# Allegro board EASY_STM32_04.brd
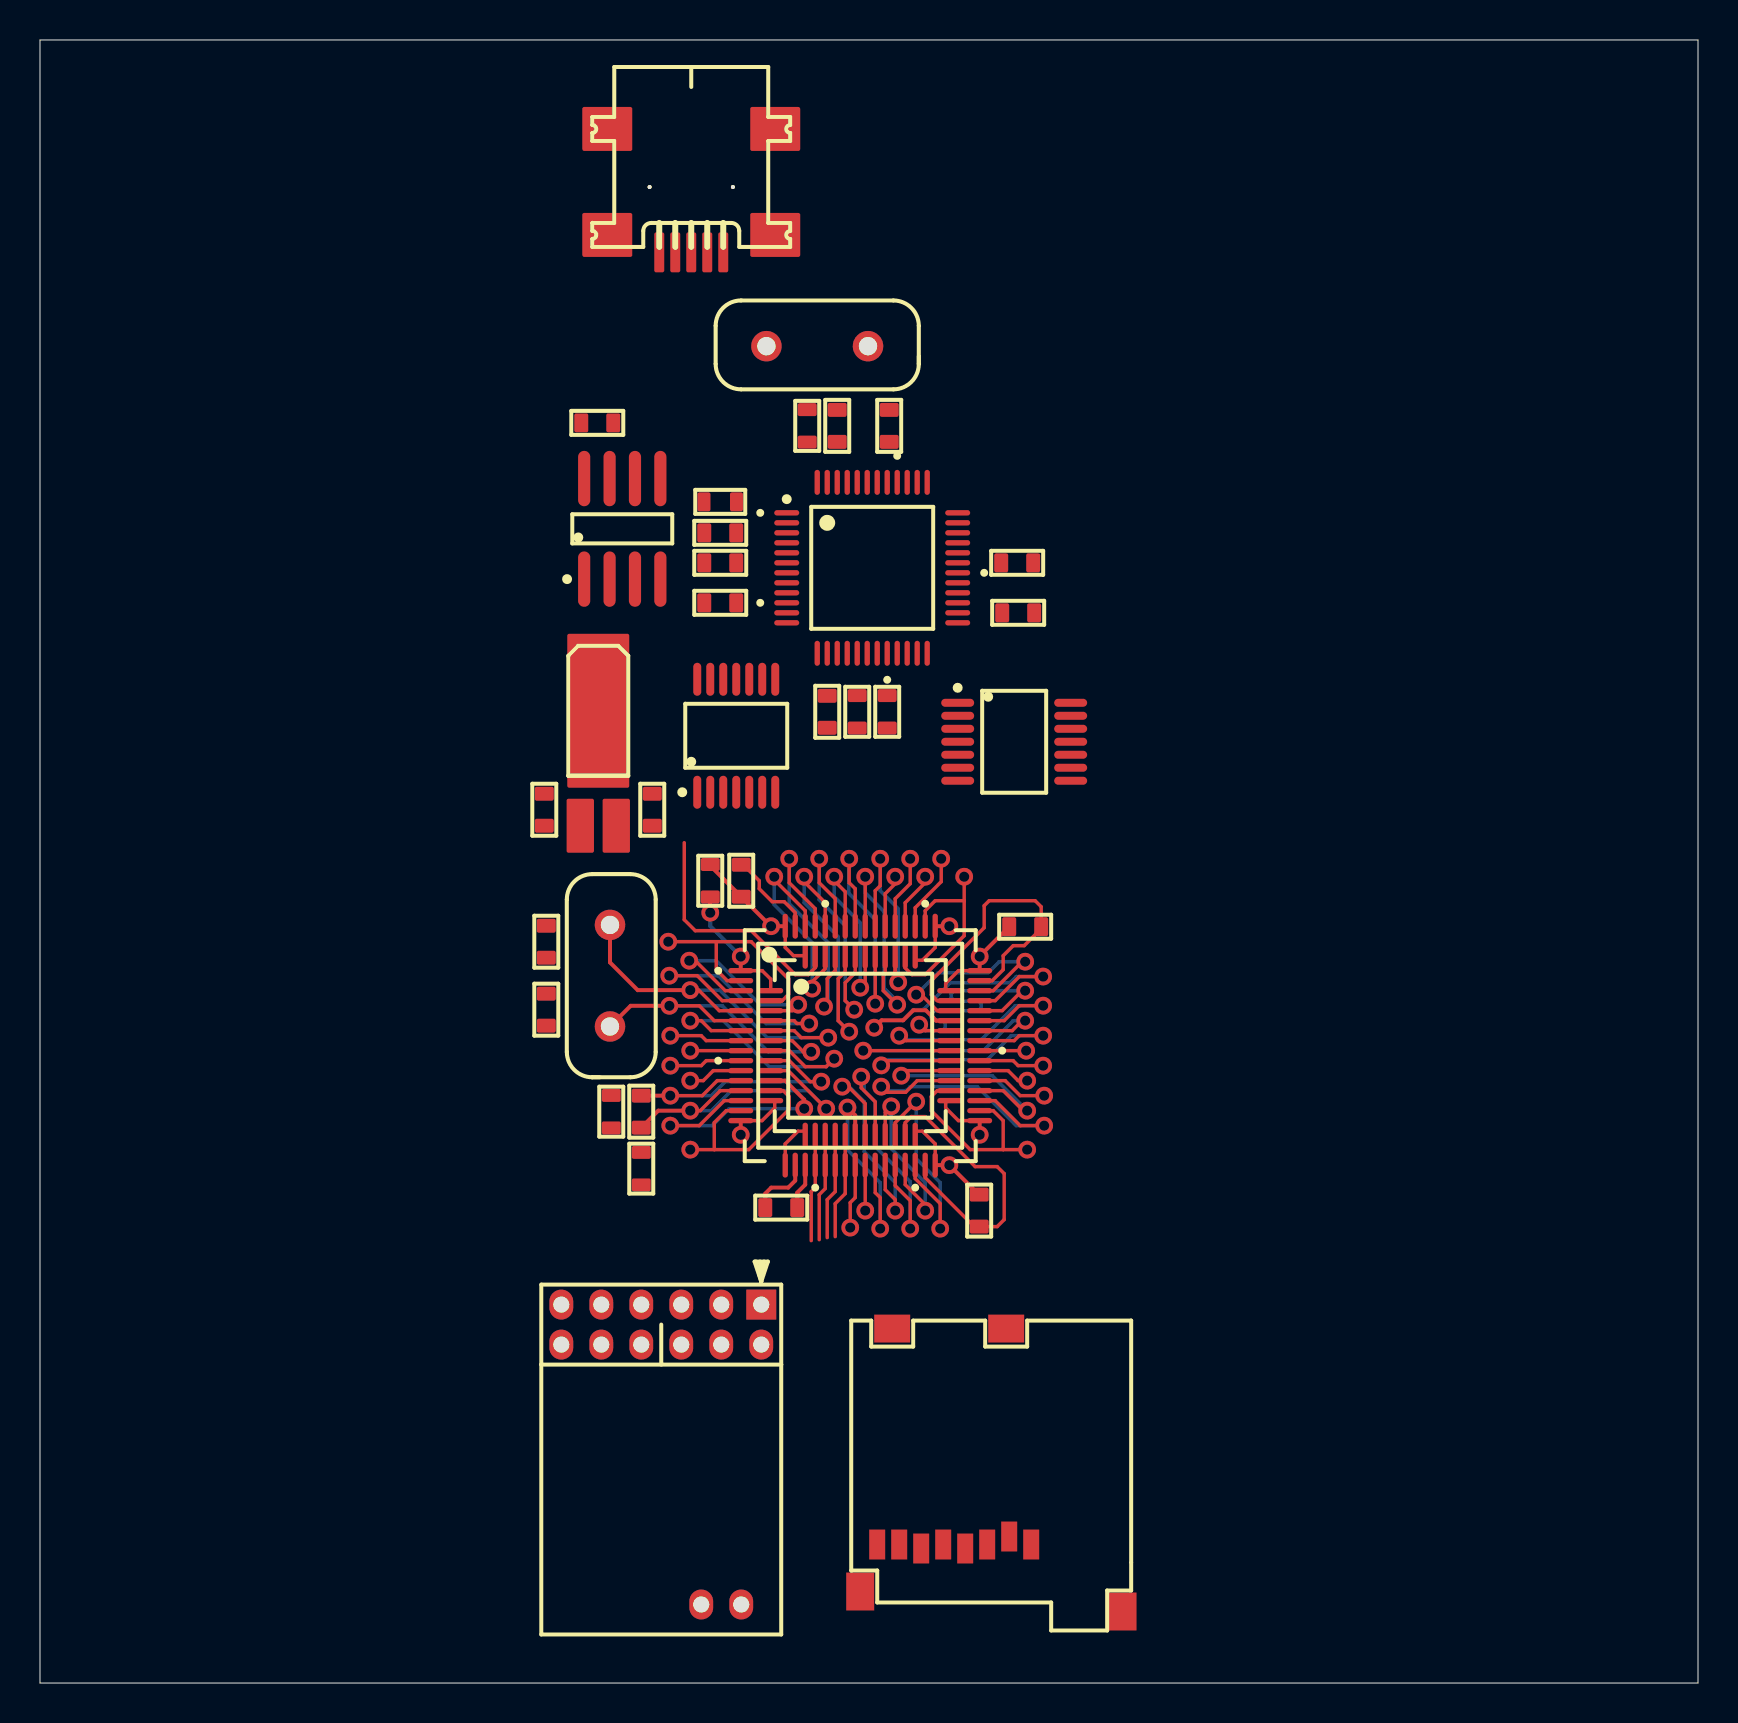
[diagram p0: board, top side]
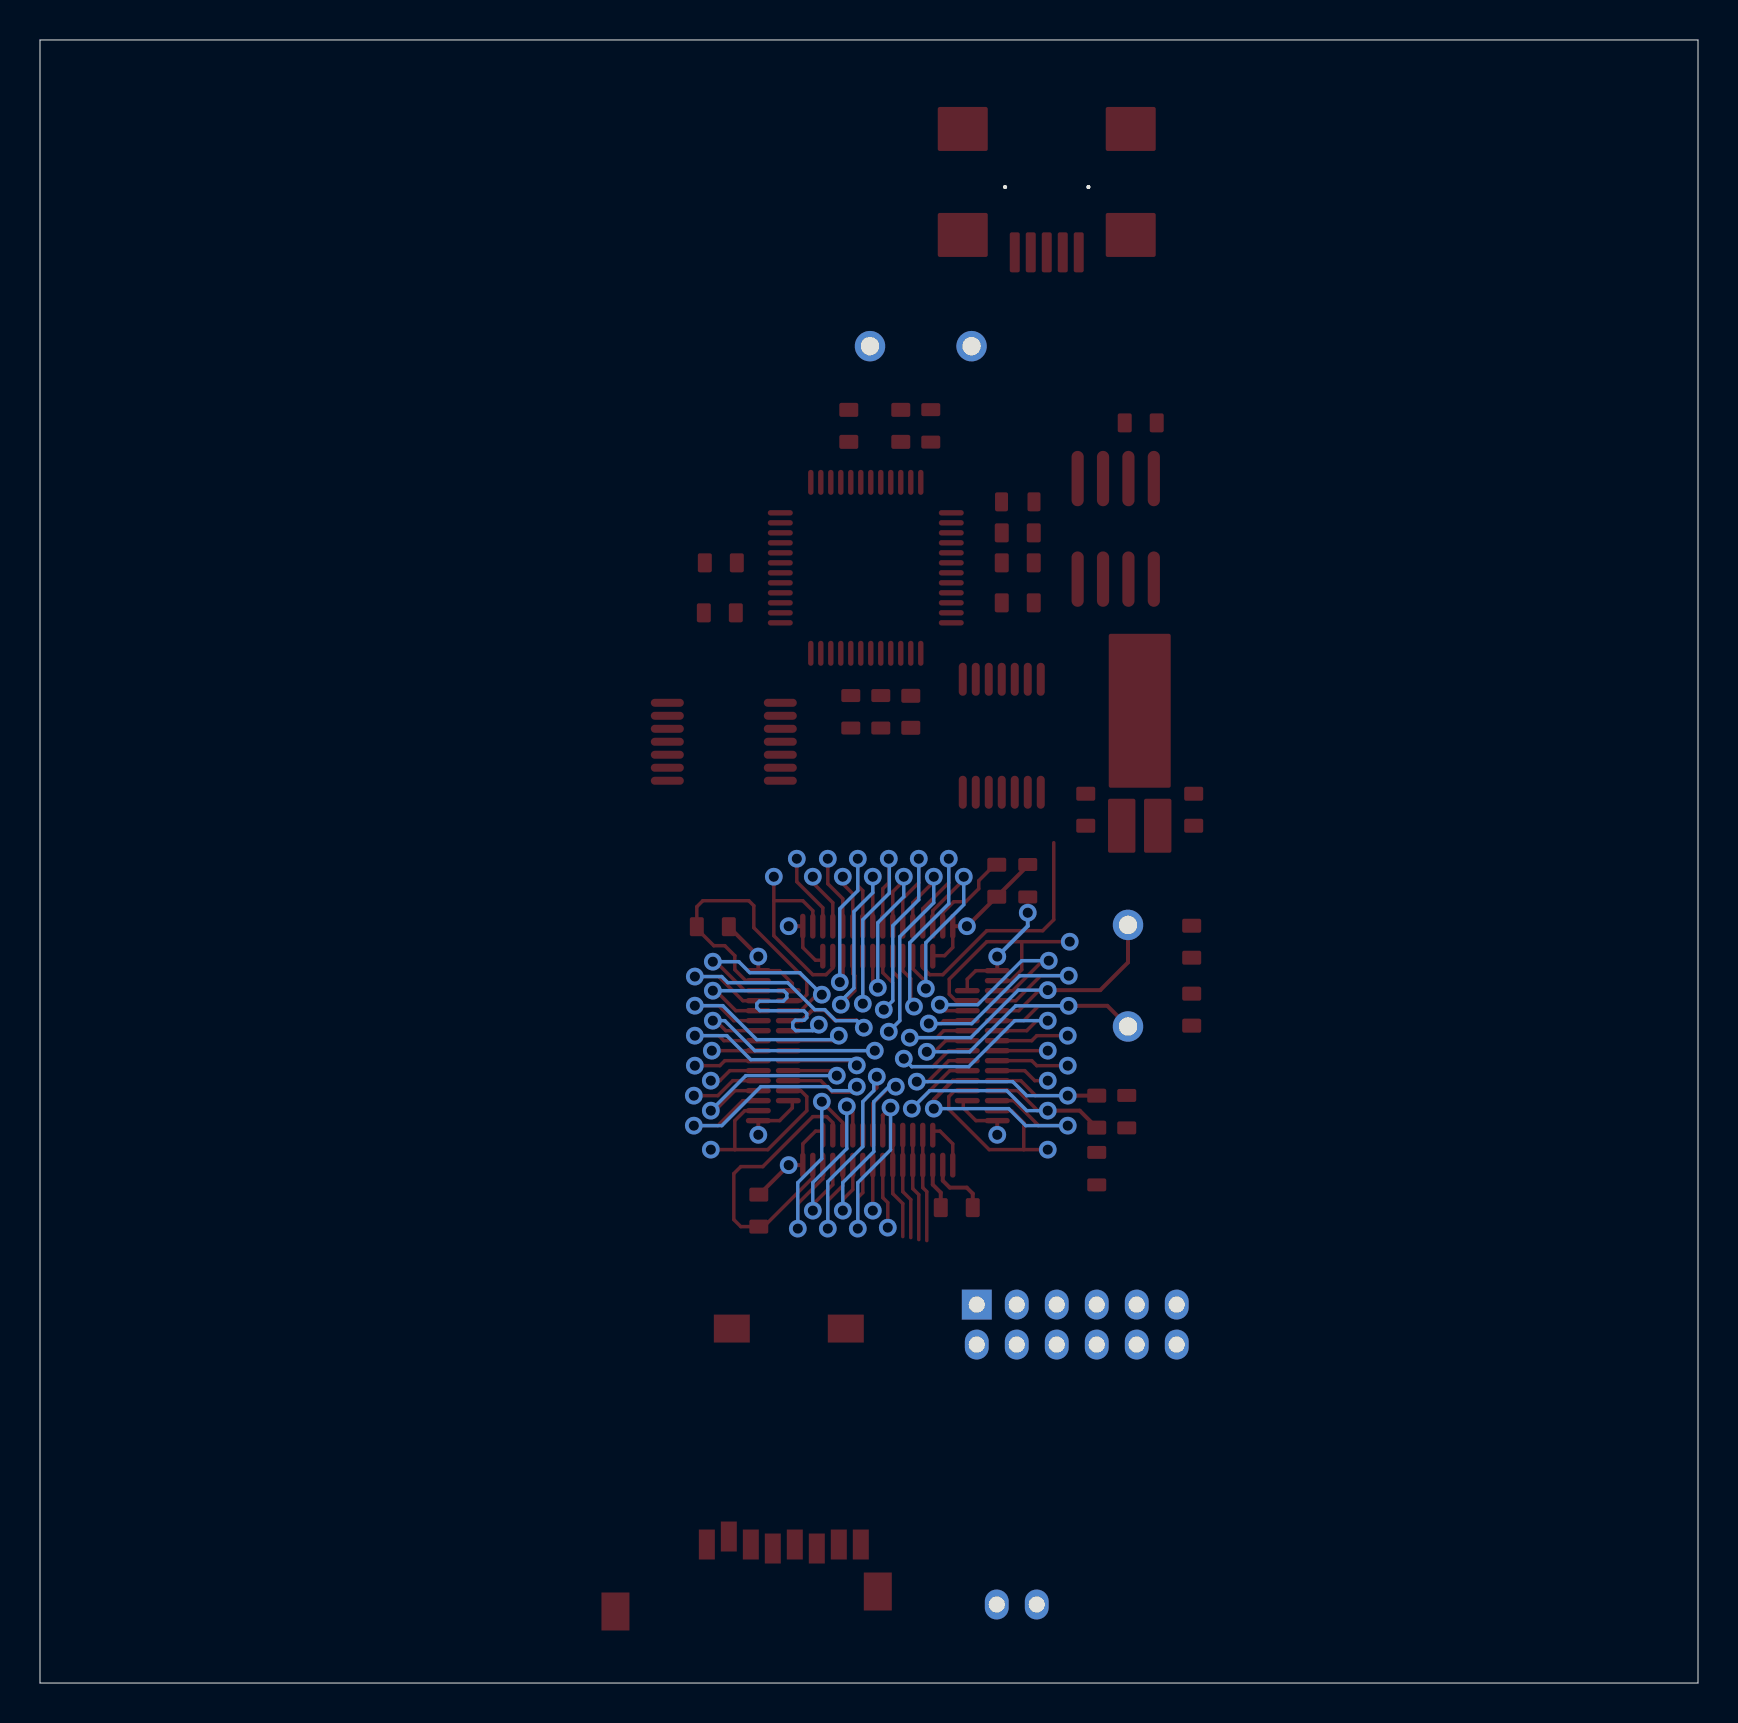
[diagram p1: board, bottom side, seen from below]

Outline 82.92 x 82.18 mm; copper layers: TOP, BOTTOM. Coordinates in mm from the lower left corner of the outline.
Outline path: 0,82.18 0,0 82.92,0 82.92,82.18 0,82.18

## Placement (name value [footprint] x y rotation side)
C1  22pF  [CAP0603_B]  25.32 37.08 270 top
C2  22p  [CAP0603_B]  25.32 33.68 90 top
C3  15p  [CAP0603_B]  25.22 43.68 90 top
C4  15p  [CAP0603_B]  30.62 43.68 90 top
C5  100n  [CAP0603_B]  30.07 28.58 90 top
C6  100n  [CAP0603_B]  46.97 23.63 270 top
C7  100n  [CAP0603_B]  49.27 37.83 0 top
C8  100n  [CAP0603_B]  35.07 40.13 90 top
C9  100n  [CAP0603_B]  37.07 23.78 180 top
C10  10u  [CAP0603_B]  27.87 63.03 0 top
C11  100n  [CAP0603_B]  34.02 57.53 180 top
C12  100n  [CAP0603_B]  42.47 62.88 90 top
C14  100n  [CAP0603_B]  34.02 54.03 180 top
C15  100n  [CAP0603_B]  39.37 48.58 270 top
C16  100n  [CAP0603_B]  48.92 53.53 0 top
C17  100n  [CAP0603_B]  48.87 56.03 0 top
C18  100n  [CAP0603_B]  39.87 62.88 90 top
C19  100n  [CAP0603_B]  34.02 56.03 180 top
J1  USB_MB  [HIROSE-US60-MB-5ST]  32.57 80.83 180 top
R1  0R  [RES0603_B]  33.52 40.13 90 top
R2  0R  [RES0603_B]  30.07 25.73 270 top
R3  0R  [RES0603_B]  28.57 28.58 270 top
R4  470R  [RES0603_B]  38.37 62.88 270 top
R7  10K  [RES0603_B]  42.37 48.58 270 top
R13  1K5  [RES0603_B]  34.02 59.08 0 top
R14  100K  [RES0603_B]  40.87 48.58 270 top
REF  val  [unnamed]  36.07 18.93 180 top
U1  STM32F103RCT6  [LQFP64_MODIFIED]  41.02 31.88 0 top
U2  STM32F100  [LQFP48L_MODIFIED]  41.02 31.88 0 top
U3  FT2232D  [LQFP48L]  41.62 55.78 0 top
U4  AT93C46-10SI-2.7  [SOIC8S1JEDECM]  29.12 57.73 0 top
U5  74LVC125A  [TSOP65P640X120-14]  48.72 47.08 270 top
U6  74LVC125A  [TSOP65P640X120-14]  34.82 47.38 0 top
U10  MICRO_SD  [MICRO_SD_PUSH]  54.57 18.13 180 top
Y1  8M  [XTAL_DIP]  28.51 32.84 90 top
Y2  32.768KHz  [RTC-CRYSTAL]  27.92 46.88 0 top
Y3  6M  [XTAL_DIP]  41.41 66.86 180 top

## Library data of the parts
C1-C9 = C1005_0: User Part Number: pn; Tolerance: RichardLC
C10-C12 C14-C19 = CAP NP_0: User Part Number: pn; Tolerance: RichardLC
J1 = CON9: User Part Number: pn; Tolerance: RichardLC
R1-R4 R7 R13 R14 = R_0: User Part Number: pn; Tolerance: RichardLC
REF = -: User Part Number: pn; Tolerance: RichardLC
U1 = STM32F103RCT6_2: User Part Number: pn; Tolerance: RichardLC
U2 = STM32F100_1: User Part Number: pn; Tolerance: RichardLC
U3 = FT2232D_0: User Part Number: pn; Tolerance: RichardLC
U4 = 93C46_2: User Part Number: pn; Tolerance: RichardLC
U5 U6 = 74HC125/LCC_0: User Part Number: pn; Tolerance: RichardLC
U10 = MOLEX_uSD_0: User Part Number: pn; Tolerance: RichardLC
Y1 Y3 = ZTB: Tolerance: ***; User Part Number: ***
Y2 = ZTA_0: User Part Number: pn; Tolerance: RichardLC

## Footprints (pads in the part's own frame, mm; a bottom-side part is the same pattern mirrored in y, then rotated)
CAP0603_B
  custom 0.175x0.175 smd: 1(-0.8,0) 2(0.8,0)
HIROSE-US60-MB-5ST
  round 0.2 hole 0.9 unplated: (-2.083,6.005) (2.083,6.005)
  custom 0.125x0.125 smd: 1(-1.6,9.271) 2(-0.8,9.271) 3(0,9.271) 4(0.8,9.271) 5(1.6,9.271)
  custom 0.55x0.55 smd: 6(-4.2,3.1) 7(4.2,3.1) 8(-4.2,8.4) 9(4.2,8.4)
LQFP48L
  oval 1.25x0.27 smd: 1(-4.275,2.75) 2(-4.275,2.25) 3(-4.275,1.75) 4(-4.275,1.25) 5(-4.275,0.75) 6(-4.275,0.25) 7(-4.275,-0.25) 8(-4.275,-0.75) 9(-4.275,-1.25) 10(-4.275,-1.75) 11(-4.275,-2.25) 12(-4.275,-2.75) 25(4.275,-2.75) 26(4.275,-2.25) 27(4.275,-1.75) 28(4.275,-1.25) 29(4.275,-0.75) 30(4.275,-0.25) 31(4.275,0.25) 32(4.275,0.75) 33(4.275,1.25) 34(4.275,1.75) 35(4.275,2.25) 36(4.275,2.75)
  oval 0.27x1.25 smd: 13(-2.75,-4.275) 14(-2.25,-4.275) 15(-1.75,-4.275) 16(-1.25,-4.275) 17(-0.75,-4.275) 18(-0.25,-4.275) 19(0.25,-4.275) 20(0.75,-4.275) 21(1.25,-4.275) 22(1.75,-4.275) 23(2.25,-4.275) 24(2.75,-4.275) 37(2.75,4.275) 38(2.25,4.275) 39(1.75,4.275) 40(1.25,4.275) 41(0.75,4.275) 42(0.25,4.275) 43(-0.25,4.275) 44(-0.75,4.275) 45(-1.25,4.275) 46(-1.75,4.275) 47(-2.25,4.275) 48(-2.75,4.275)
LQFP48L_MODIFIED
  oval 1.25x0.27 smd: 1(-4.475,2.75) 2(-4.475,2.25) 3(-4.475,1.75) 4(-4.475,1.25) 5(-4.475,0.75) 6(-4.475,0.25) 7(-4.475,-0.25) 8(-4.475,-0.75) 9(-4.475,-1.25) 10(-4.475,-1.75) 11(-4.475,-2.25) 12(-4.475,-2.75) 25(4.475,-2.75) 26(4.475,-2.25) 27(4.475,-1.75) 28(4.475,-1.25) 29(4.475,-0.75) 30(4.475,-0.25) 31(4.475,0.25) 32(4.475,0.75) 33(4.475,1.25) 34(4.475,1.75) 35(4.475,2.25) 36(4.475,2.75)
  oval 0.27x1.25 smd: 13(-2.75,-4.475) 14(-2.25,-4.475) 15(-1.75,-4.475) 16(-1.25,-4.475) 17(-0.75,-4.475) 18(-0.25,-4.475) 19(0.25,-4.475) 20(0.75,-4.475) 21(1.25,-4.475) 22(1.75,-4.475) 23(2.25,-4.475) 24(2.75,-4.475) 37(2.75,4.475) 38(2.25,4.475) 39(1.75,4.475) 40(1.25,4.475) 41(0.75,4.475) 42(0.25,4.475) 43(-0.25,4.475) 44(-0.75,4.475) 45(-1.25,4.475) 46(-1.75,4.475) 47(-2.25,4.475) 48(-2.75,4.475)
LQFP64_MODIFIED
  oval 1.25x0.27 smd: 1(-5.975,3.75) 2(-5.975,3.25) 3(-5.975,2.75) 4(-5.975,2.25) 5(-5.975,1.75) 6(-5.975,1.25) 7(-5.975,0.75) 8(-5.975,0.25) 9(-5.975,-0.25) 10(-5.975,-0.75) 11(-5.975,-1.25) 12(-5.975,-1.75) 13(-5.975,-2.25) 14(-5.975,-2.75) 15(-5.975,-3.25) 16(-5.975,-3.75) 33(5.975,-3.75) 34(5.975,-3.25) 35(5.975,-2.75) 36(5.975,-2.25) 37(5.975,-1.75) 38(5.975,-1.25) 39(5.975,-0.75) 40(5.975,-0.25) 41(5.975,0.25) 42(5.975,0.75) 43(5.975,1.25) 44(5.975,1.75) 45(5.975,2.25) 46(5.975,2.75) 47(5.975,3.25) 48(5.975,3.75)
  oval 0.27x1.25 smd: 17(-3.75,-5.975) 18(-3.25,-5.975) 19(-2.75,-5.975) 20(-2.25,-5.975) 21(-1.75,-5.975) 22(-1.25,-5.975) 23(-0.75,-5.975) 24(-0.25,-5.975) 25(0.25,-5.975) 26(0.75,-5.975) 27(1.25,-5.975) 28(1.75,-5.975) 29(2.25,-5.975) 30(2.75,-5.975) 31(3.25,-5.975) 32(3.75,-5.975) 49(3.75,5.975) 50(3.25,5.975) 51(2.75,5.975) 52(2.25,5.975) 53(1.75,5.975) 54(1.25,5.975) 55(0.75,5.975) 56(0.25,5.975) 57(-0.25,5.975) 58(-0.75,5.975) 59(-1.25,5.975) 60(-1.75,5.975) 61(-2.25,5.975) 62(-2.75,5.975) 63(-3.25,5.975) 64(-3.75,5.975)
MICRO_SD_PUSH
  rect 0.8x1.5 smd: 1(5,11.2) 2(6.1,10.8) 3(7.2,11.2) 4(8.3,11.4) 5(9.4,11.2) 6(10.5,11.4) 7(11.6,11.2) 8(12.7,11.2)
  rect 1.4x1.9 smd: G1(0.43,14.55) G2(13.55,13.55)
  rect 1.8x1.4 smd: S1(6.25,0.4) S2(11.95,0.4)
RES0603_B
  custom 0.163x0.163 smd: 1(-0.812,0) 2(0.812,0)
RTC-CRYSTAL
  custom 0.343x0.343 smd: 1(-0.9,-4) 2(0.9,-4)
  custom 0.775x0.775 smd: 3(0,1.75)
SOIC8S1JEDECM
  oval 0.61x2.77 smd: 1(-1.905,-2.515) 2(-0.635,-2.515) 3(0.635,-2.515) 4(1.905,-2.515) 5(1.905,2.515) 6(0.635,2.515) 7(-0.635,2.515) 8(-1.905,2.515)
TSOP65P640X120-14
  oval 0.4x1.65 smd: 1(-1.95,-2.825) 2(-1.3,-2.825) 3(-0.65,-2.825) 4(0,-2.825) 5(0.65,-2.825) 6(1.3,-2.825) 7(1.95,-2.825) 8(1.95,2.825) 9(1.3,2.825) 10(0.65,2.825) 11(0,2.825) 12(-0.65,2.825) 13(-1.3,2.825) 14(-1.95,2.825)
unnamed
  rect 1.5x1.5 hole 0.8: 1(0,0)
  oval 1.194x1.499 hole 0.8: 2(0,2) 3(2,0) 4(2,2) 5(4,0) 6(4,2) 7(6,0) 8(6,2) 9(8,0) 10(8,2) 11(10,0) 12(10,2) 13(1,15) 14(3,15)
XTAL_DIP
  round 1.524 hole 0.914: 1(0,0) 2(5.08,0)

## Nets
+3V3: C6.1 C7.1 C8.1 C9.1 C14.1 C15.1 C16.1 C17.1 R1.2 R2.2 R14.1 U1.19(VDD_4) U1.32(VDD_1) U1.48(VDD_2) U1.64(VDD_3) U2.24(VDD_1) U2.36(VDD_2) U2.48(VDD_3) U3.10(SI/WUA) U3.14(VCCIOA) U3.17(ADBUS6) U3.26(SI/WUB) U3.31(VCCIOB) U5.14(VCC) U10.4(VDD)
+5V: C10.1 C11.1 C12.1 R4.1 U3.3(VCC1) U3.42(VCC2) U4.8(VCC)
GND: C1.2 C2.2 C3.2 C4.2 C6.2 C7.2 C8.2 C9.2 C10.2 C11.2 C12.2 C14.2 C15.2 C16.2 C17.2 C18.2 C19.2 J1.5 J1.6 J1.7 J1.8 J1.9 R3.2 R7.2 R14.2 U1.18(VSS_4) U1.31(VSS_1) U1.47(VSS_2) U1.63(VSS_3) U2.23(VSS_1) U2.35(VSS_2) U2.47(VSS_3) U3.9(GND1) U3.18(GND2) U3.25(GND3) U3.34(GND4) U3.45(AGND) U3.47(TEST) U4.5(GND) U4.7(NC) U5.7(GND) U6.7(GND) U10.6(VSS) Y2.3
VBAT: R1.1 U1.1(VBAT) U2.1(VBAT)
VCC: U6.14(VCC)
VDDA: C5.1 R2.1 U1.13(VDDA) U2.9(VDDA)
VSSA: C5.2 R3.1 U1.12(VSSA) U2.8(VSSA)
BOOT0: U1.60(BOOT0) U2.44(BOOT0)
CTS: U3.37(BDBUS3)
DCD: U3.33(BDBUS6)
DSR: U3.35(BDBUS5)
DTR: U3.36(BDBUS4)
EECK: U3.1(EESK) U4.2(CLK)
EECS: U3.48(EECS) U4.1(CS)
EEDA: U3.2(EEDATA) U4.3(DI)
JT_SRSTN: U3.16(ADBUS7)
MMC1_CD: U10.G2
MMC1_CLK: U10.5(CLK)
MMC1_CMD: U10.3(CMD/DI)
MMC1_D0: U10.7(DAT0/DO)
MMC1_D1: U10.8(DAT1/RSV)
MMC1_D2: U10.1(DAT2/NC)
MMC1_D3: U10.2(CD/C\S\/DAT3)
NRST: U1.7(NRST) U2.7(NRST)
OSC32_IN: C4.1 U1.3(PC14/OSC32_IN) U2.3(PC14/OSC32_IN) Y2.2
OSC32_OUT: C3.1 U1.4(PC15/OSC32/OUT) U2.4(PC15/OSC32_OUT) Y2.1
OSC_IN: C1.1 U1.5(PD0/OSC_IN) U2.5(PD0/OSC_IN) Y1.2
OSC_OUT: C2.1 U1.6(PD1/OSC_OUT) U2.6(PD1/OSC_OUT) Y1.1
PA0: U1.14(PA0-WKUP) U2.10(PA0/WKUP)
PA1: U1.15(PA1) U2.11(PA1)
PA2: U1.16(PA2) U2.12(PA2)
PA3: U1.17(PA3) U2.13(PA3)
PA4: U1.20(PA4) U2.14(PA4)
PA5: U1.21(PA5) U2.15(PA5)
PA6: U1.22(PA6) U2.16(PA6)
PA7: U1.23(PA7) U2.17(PA7)
PA8: U1.41(PA8) U2.29(PA8)
PA9: U1.42(PA9) U2.30(PA9)
PA10: U1.43(PA10) U2.31(PA10)
PA11: U1.44(PA11) U2.32(PA11)
PA12: U1.45(PA12) U2.33(PA12)
PA13: U1.46(PA13) U2.34(PA13)
PA14: U1.49(PA14) U2.37(PA14)
PA15: U1.50(PA15) U2.38(PA15)
PB0: U1.26(PB0) U2.18(PB0)
PB1: U1.27(PB1) U2.19(PB1)
PB2: U1.28(PB2/BOOT1) U2.20(PB2)
PB3: U1.55(PB3) U2.39(PB3)
PB4: U1.56(PB4) U2.40(PB4)
PB5: U1.57(PB5) U2.41(PB5)
PB6: U1.58(PB6) U2.42(PB6)
PB7: U1.59(PB7) U2.43(PB7)
PB8: U1.61(PB8) U2.45(PB8)
PB9: U1.62(PB9) U2.46(PB9)
PB10: U1.29(PB10) U2.21(PB10)
PB11: U1.30(PB11) U2.22(PB11)
PB12: U1.33(PB12) U2.25(PB12)
PB13: U1.34(PB13) U2.26(PB13)
PB14: U1.35(PB14) U2.27(PB14)
PB15: U1.36(PB15) U2.28(PB15)
PC0: U1.8(PC0)
PC1: U1.9(PC1)
PC2: U1.10(PC2)
PC3: U1.11(PC3)
PC4: U1.24(PC4)
PC5: U1.25(PC5)
PC6: U1.37(PC6)
PC7: U1.38(PC7)
PC8: U1.39(PC8)
PC9: U1.40(PC9)
PC10: U1.51(PC10)
PC11: U1.52(PC11)
PC12: U1.53(PC12)
PC13: U1.2(PC13/TAMPER/RTC) U2.2(PC13/TAMPER/RTC)
PD2: U1.54(PD2)
RI: U3.32(BDBUS7)
RTS: U3.38(BDBUS2)
RXD: U3.39(BDBUS1)
SRST: U3.11(ACBUS3)
SRST_OE: U3.12(ACBUS2)
TRST: U3.13(ACBUS1)
TRST_OE: U3.15(ACBUS0)
TXD: U3.40(BDBUS0)
USB_CLK: U3.24(ADBUS0) U5.12(A4)
USB_TDI: U3.23(ADBUS1) U5.9(A3)
USB_TDO: U3.22(ADBUS2) U5.2(A1)
USB_TMS: U3.21(ADBUS3) U5.5(A2)
N50123: J1.3 R13.1 U3.7(USBDP)
N50127: C18.1 R4.2 U3.46(AVCC)
N50535: R7.1 U3.20(ADBUS4)
N50793: U3.43(XTIN) Y3.1
N50801: U3.44(XTOUT) Y3.2
N51025: J1.1
N51319: R13.2 U3.5(R\S\T\O\U\T\)
N51335: J1.2 U3.8(USBDM)
N51347: U3.4(R\E\S\E\T\)
N51363: C19.1 U3.6(3V3OUT)
N51511: U4.4(DO)
N70305: U10.S2

Pads without a net: J1 4; REF 1 2 3 4 5 6 7 8 9 10 11 12 13 14; U3 19 27 28 29 30 41; U4 6; U5 1 3 4 6 8 10 11 13; U6 1 2 3 4 5 6 8 9 10 11 12 13; U10 G1 S1

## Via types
v1: diameter 0.889, hole 0.508, TOP to BOTTOM, 84 vias

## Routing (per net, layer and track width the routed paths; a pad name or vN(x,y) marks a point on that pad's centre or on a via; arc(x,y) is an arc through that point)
+3V3: length 19.8
  TOP w0.175: U1.32 44.77,26.97 44.13,27.6 43.77,27.6 ; 38.27,36.38 37.68,36.38 37.27,36.79 U1.64 ; U1.48 45.93,35.63 45.3,34.99 45.3,34.63
  TOP w0.2: U1.19 38.27,24.93 37.87,24.53 C9.1 ; R1.2 33.52,40.88 C8.1 36.55,37.85 v1(36.56,37.85) U1.64 ; 46.95,24.43 v1(45.48,25.9) U1.32 ; C7.1 47,36.35 v1(47,36.33) U1.48
GND: length 50.2
  TOP w0.175: U2.47 38.77,35.78 38.42,35.43 37.77,35.43 35.57,37.63 32.77,37.63 32.22,38.18 32.22,42.03 ; C8.2 35.17,40.93 35.97,40.13 35.97,39.73 36.62,39.08 37.22,39.08 37.77,38.53 U1.63 ; U2.35 44.87,34.13 44.57,34.43 44.57,35.13 47.22,37.78 47.22,38.88 47.47,39.13 49.77,39.13 50.07,38.83 C7.2 50.07,37.73 49.22,36.88 48.67,36.88 48.17,36.38 48.17,35.68 47.62,35.13 U1.47 ; 43.27,27.6 43.27,28.03 43.57,28.33 44.27,28.33 46.77,25.83 47.87,25.83 48.22,25.48 48.22,23.18 47.87,22.83 C6.2 46.72,22.83 44.27,25.28 U1.31
  TOP w0.2: U1.18 37.77,25.13 37.42,24.78 36.57,24.78 36.27,24.48 C9.2
VBAT: length 6.6
  TOP w0.175: U2.1 36.55,35.2 36.12,35.63 U1.1
  TOP w0.2: U1.1 v1(35.05,36.33) ; R1.1 v1(33.52,38.53)
  BOTTOM w0.2: v1(33.52,38.53) 33.52,37.86 v1(35.05,36.33)
VDDA: length 16.9
  TOP w0.175: v1(32.52,28.63) 33.02,28.63 34.02,29.63 U1.13 ; v1(39.32,28.73) 37.42,30.63 U2.9
  TOP w0.2: C5.1 30.92,28.63 v1(32.52,28.63)
  BOTTOM w0.175: v1(32.52,28.63) 33.57,28.63 34.57,29.63 38.42,29.63 v1(39.32,28.73)
VSSA: length 16.1
  TOP w0.175: v1(31.52,29.38) 33.12,29.38 33.87,30.13 U1.12 ; U2.8 37.47,31.13 38.52,30.08 v1(39.07,30.08)
  TOP w0.2: v1(31.52,29.38) C5.2
  BOTTOM w0.175: v1(31.52,29.38) 33.57,29.38 34.27,30.08 v1(39.07,30.08)
BOOT0: length 15.7
  TOP w0.175: U1.60 39.27,39.03 38.22,40.08 v1(38.22,40.33) ; v1(40.47,32.58) 39.92,33.13 39.92,35.23 40.27,35.58 U2.44
  BOTTOM w0.175: v1(40.47,32.58) 39.92,33.13 39.92,37.33 38.22,39.03 v1(38.22,40.33)
NRST: length 14.7
  TOP w0.175: v1(39.72,31.23) 39.32,30.83 38.27,30.83 37.47,31.63 U2.7 ; v1(32.52,33.13) 33.07,33.13 33.57,32.63 U1.7
  BOTTOM w0.175: v1(39.72,31.23) 39.32,30.83 36.47,30.83 34.17,33.13 v1(32.52,33.13)
OSC32_IN: length 11.1
  TOP w0.175: v1(37.92,33.93) 37.62,33.63 U2.3 ; U1.3 34.27,34.63 32.77,36.13 v1(32.47,36.13)
  BOTTOM w0.175: v1(37.92,33.93) 36.02,33.93 33.82,36.13 v1(32.47,36.13)
OSC32_OUT: length 14.1
  TOP w0.175: v1(31.47,35.38) 32.87,35.38 34.12,34.13 U1.4 ; v1(38.47,32.98) 37.86,32.98 37.72,33.13 U2.4
  BOTTOM w0.175: v1(31.47,35.38) 33.92,35.38 36.32,32.98 38.46,32.98 v1(38.47,32.98)
OSC_IN: length 20.3
  TOP w0.175: U1.5 33.97,33.63 32.94,34.66 v1(32.52,34.66) ; v1(39.42,32.28) 38.07,32.28 37.72,32.63 U2.5
  TOP w0.2: v1(32.52,34.66) 29.89,34.66 28.51,36.04 Y1.2
  BOTTOM w0.175: v1(32.52,34.66) 33.99,34.66 36.37,32.28 v1(39.42,32.28)
OSC_OUT: length 17.6
  TOP w0.175: U2.6 37.62,32.13 38.18,31.57 v1(38.57,31.57) ; v1(31.48,33.87) 32.98,33.87 33.72,33.13 U1.6
  TOP w0.2: Y1.1 29.54,33.87 v1(31.48,33.87)
  BOTTOM w0.175: v1(38.57,31.57) 36.43,31.57 34.13,33.87 v1(31.48,33.87)
PA0: length 13.6
  TOP w0.175: v1(31.52,27.88) 32.97,27.88 34.22,29.13 U1.14
  TOP w0.2: v1(38.22,28.73) 38.22,29.18 37.27,30.13 U2.10
  BOTTOM w0.175: v1(38.22,28.73) 34.47,28.73 33.62,27.88 v1(31.52,27.88)
PA1: length 10.2
  TOP w0.175: v1(32.52,26.68) 33.72,26.68 ; 33.72,26.68 35.45,26.68 37.47,28.7 37.47,29.33 37.17,29.63 36.75,29.63 ; 33.72,26.68 33.72,28.03 34.32,28.63 U1.15
PA2: length 3
  TOP w0.175: 36.75,29.13 36.75,28.76 36.11,28.13 U1.16
  TOP w0.2: U1.16 v1(35.05,27.42)
PA3: length 2.3
  TOP w0.175: U1.17 37.27,26.97 37.91,27.6 38.27,27.6
PA4: length 5.6
  TOP w0.175: 38.77,27.6 U2.14 U1.20 38.77,24.78 38.57,24.58 38.57,22.13
PA5: length 5.5
  TOP w0.175: 38.97,22.18 38.97,24.43 39.27,24.73 U1.21 U2.15 39.27,27.6
PA6: length 5.5
  TOP w0.175: 39.37,22.28 39.37,24.18 39.77,24.58 U1.22 U2.16 39.77,27.6
PA7: length 5.5
  TOP w0.175: 40.27,27.6 U2.17 U1.23 40.27,24.48 39.77,23.98 39.77,22.33
PA8: length 15.5
  TOP w0.175: v1(42.07,30.89) 42.09,30.89 42.32,31.13 U2.29 ; U1.41 48.72,32.13 48.97,32.38 v1(50.17,32.38)
  BOTTOM w0.175: v1(42.07,30.89) 42.36,31.18 47.37,31.18 48.57,32.38 v1(50.17,32.38)
PA9: length 15.5
  TOP w0.175: v1(49.27,33.13) 49.12,33.13 48.62,32.63 U1.42 ; v1(41.17,31.63) U2.30
  BOTTOM w0.175: v1(41.17,31.63) 47.17,31.63 48.67,33.13 v1(49.27,33.13)
PA10: length 14.1
  TOP w0.175: U2.31 43.32,32.13 43.07,32.38 v1(42.97,32.38) ; U1.43 48.22,33.13 48.97,33.88 v1(50.17,33.88)
  BOTTOM w0.175: v1(50.17,33.88) 48.77,33.88 47.07,32.18 43.17,32.18 v1(42.97,32.38)
PA11: length 15.5
  TOP w0.175: v1(49.27,34.63) 49.12,34.63 48.12,33.63 U1.44 ; v1(43.97,32.93) 44.27,32.63 U2.32
  BOTTOM w0.175: v1(49.27,34.63) 45.72,34.63 45.57,34.48 45.57,34.28 45.75,34.1 46.95,34.1 47.07,33.98 47.07,33.78 46.92,33.63 44.72,33.63 44.57,33.48 44.57,33.28 44.7,33.15 45.15,33.15 45.27,33.03 45.27,32.78 45.12,32.63 44.27,32.63 v1(43.97,32.93)
PA12: length 17.5
  TOP w0.175: v1(50.17,35.33) 48.98,35.33 47.77,34.13 U1.45
  TOP w0.2: v1(41.72,32.78) 42.09,33.15 43.17,33.15 43.67,33.65 44.3,33.65 44.82,33.13 U2.33
  BOTTOM w0.175: v1(41.72,32.78) 42.07,33.13 43.12,33.13 43.67,33.68 44.17,33.68 45.52,35.03 48.52,35.03 48.83,35.33 v1(50.17,35.33)
PA13: length 11
  TOP w0.175: U2.34 44.87,33.63 44.07,34.43 v1(43.82,34.43) ; U1.46 47.67,34.63 49.12,36.08 v1(49.27,36.08)
  BOTTOM w0.175: v1(43.82,34.43) 44.92,35.53 47.42,35.53 47.97,36.08 v1(49.27,36.08)
PA14: length 3
  TOP w0.175: 43.77,36.15 44.13,36.15 44.77,36.79 U1.49
  TOP w0.2: U1.49 v1(45.48,37.85)
PA15: length 10.4
  TOP w0.175: 46.22,39.13 44.77,39.13 44.27,38.63 U1.50 ; 46.22,39.13 46.22,37.38 44.27,35.43 43.61,35.43 43.27,35.77 U2.38 ; 46.22,39.13 v1(46.22,40.33)
PB0: length 11.5
  TOP w0.175: v1(42.02,22.73) 42.02,24.28 41.77,24.53 U1.26
  TOP w0.2: U2.18 40.77,28.39 v1(40.38,28.78)
  BOTTOM w0.175: v1(40.38,28.78) 40.38,26.66 42.02,25.03 v1(42.02,22.73)
PB1: length 13.1
  TOP w0.175: U1.27 42.27,24.68 42.77,24.18 v1(42.77,23.63) ; v1(40.12,29.83) 40.42,29.83 41.27,28.98 U2.19
  BOTTOM w0.175: v1(40.12,29.83) 40.47,29.83 41.22,29.08 41.22,26.58 42.77,25.03 v1(42.77,23.63)
PB2: length 15.3
  TOP w0.175: U1.28 42.77,24.88 43.52,24.13 v1(43.52,22.73) ; v1(41.07,30.33) 41.07,29.77 41.77,29.07 U2.20
  BOTTOM w0.175: v1(41.07,30.33) 41.22,30.18 41.22,29.63 41.77,29.08 41.77,26.83 43.52,25.08 v1(43.52,22.73)
PB3: length 11.4
  TOP w0.175: U1.55 41.77,39.63 42.02,39.88 v1(42.02,41.23)
  TOP w0.2: U2.39 42.77,35.2 v1(42.92,35.05)
  BOTTOM w0.175: v1(42.92,35.05) 42.92,38.73 42.02,39.63 v1(42.02,41.23)
PB4: length 12.3
  TOP w0.175: U2.40 42.27,35.48 42.17,35.38 42.17,34.63 v1(42.87,33.93) ; U1.56 v1(41.27,40.33)
  BOTTOM w0.175: v1(41.27,40.33) 41.27,39.53 42.21,38.58 42.21,34.76 42.87,34.1 v1(42.87,33.93)
PB5: length 13.7
  TOP w0.175: U1.57 40.77,39.73 40.47,40.03 v1(40.47,41.23) ; U2.41 v1(41.77,33.98)
  BOTTOM w0.175: v1(40.47,41.23) 40.45,41.2 40.45,39.5 41.77,38.18 v1(41.77,33.98)
PB6: length 10.5
  TOP w0.175: U1.58 40.27,39.58 39.72,40.13 v1(39.72,40.33) ; U2.42 41.27,35.03 v1(41.02,34.78)
  BOTTOM w0.175: v1(41.02,34.78) 41.02,38.03 39.72,39.33 v1(39.72,40.33)
PB7: length 15
  TOP w0.175: U1.59 39.77,39.23 38.97,40.03 v1(38.97,41.23) ; v1(40.72,33.68) 40.27,34.13 40.27,35.03 40.77,35.53 U2.43
  BOTTOM w0.175: v1(38.97,41.23) 38.97,39.18 40.27,37.88 40.27,34.13 v1(40.72,33.68)
PB8: length 15
  TOP w0.175: U1.61 38.77,38.73 37.47,40.03 v1(37.47,41.23) ; v1(39.21,33.83) 39.37,33.99 39.37,35.23 39.77,35.63 U2.45
  BOTTOM w0.175: v1(37.47,41.23) 37.47,38.98 39.42,37.03 39.42,34.04 v1(39.21,33.83)
PB9: length 11.4
  TOP w0.175: U1.62 38.27,38.63 36.72,40.18 v1(36.72,40.33) ; v1(38.62,34.73) 38.62,35.07 39.27,35.73 U2.46
  BOTTOM w0.175: v1(38.62,34.73) 38.62,37.03 36.72,38.93 v1(36.72,40.33)
PB10: length 10.2
  TOP w0.175: U2.21 42.27,28.54 v1(42.57,28.84) ; U1.29 43.27,24.93 44.27,23.93 v1(44.27,23.63)
  BOTTOM w0.175: v1(42.57,28.84) 42.57,26.73 44.27,25.03 v1(44.27,23.63)
PB11: length 12.6
  TOP w0.175: v1(45.02,22.73) 45.02,23.98 43.77,25.23 U1.30 ; v1(43.82,29.08) 42.77,28.03 U2.22
  BOTTOM w0.175: v1(45.02,22.73) 45.02,25.03 43.82,26.23 v1(43.82,29.08)
PB12: length 3
  TOP w0.175: U1.33 45.93,28.13 45.3,28.76 45.3,29.13
  TOP w0.2: U1.33 v1(47,27.42)
PB13: length 10
  TOP w0.175: U1.34 47.67,28.63 48.17,28.13 48.17,26.68 ; 45.3,29.63 44.87,29.63 44.57,29.33 44.57,28.63 46.52,26.68 48.17,26.68 ; 48.17,26.68 v1(49.37,26.68)
PB14: length 16.6
  TOP w0.175: v1(50.22,27.88) 49.02,27.88 47.77,29.13 U1.35 ; v1(42.07,29.83) 42.35,29.55 43.29,29.55 43.87,30.13 U2.27
  BOTTOM w0.175: v1(50.22,27.88) 48.82,27.88 46.87,29.83 43.52,29.83 43.32,29.63 42.27,29.63 v1(42.07,29.83)
PB15: length 12.3
  TOP w0.175: U1.36 48.17,29.63 49.17,28.63 v1(49.37,28.63) ; U2.28 43.32,30.63 v1(43.07,30.38)
  BOTTOM w0.175: v1(49.37,28.63) 47.62,30.38 v1(43.07,30.38)
PC0: length 3.6
  TOP w0.175: U1.8 33.32,32.13 33.07,32.38 v1(31.52,32.38)
PC1: length 2.5
  TOP w0.175: U1.9 v1(32.52,31.63)
PC2: length 3.6
  TOP w0.175: v1(31.52,30.88) 33.07,30.88 33.32,31.13 U1.10
PC3: length 2.7
  TOP w0.175: v1(32.52,30.13) 33.17,30.13 33.67,30.63 U1.11
PC4: length 3.2
  TOP w0.175: v1(40.52,22.78) 40.52,24.03 40.77,24.28 U1.24
PC5: length 2.3
  TOP w0.175: U1.25 v1(41.27,23.63)
PC6: length 3.5
  TOP w0.175: v1(50.22,29.38) 49.02,29.38 48.27,30.13 U1.37
PC7: length 2.6
  TOP w0.175: U1.38 48.42,30.63 48.92,30.13 v1(49.37,30.13)
PC8: length 3.3
  TOP w0.175: U1.39 48.67,31.13 48.92,30.88 v1(50.17,30.88)
PC9: length 2.3
  TOP w0.175: U1.40 v1(49.32,31.63)
PC10: length 3.9
  TOP w0.175: U1.51 43.77,38.78 45.07,40.08 v1(45.07,41.23)
PC11: length 2.9
  TOP w0.175: v1(44.27,40.33) 44.27,40.03 43.27,39.03 U1.52
PC12: length 3.7
  TOP w0.175: U1.53 42.77,39.23 43.52,39.98 v1(43.52,41.23)
PC13: length 11.4
  TOP w0.175: 33.82,37.08 33.82,35.68 34.37,35.13 U1.2 ; 33.82,37.08 35.57,37.08 37.45,35.2 37.45,34.45 37.12,34.13 U2.2 ; 33.82,37.08 v1(31.42,37.08)
PD2: length 2.7
  TOP w0.175: U1.54 42.27,39.48 42.77,39.98 v1(42.77,40.33)

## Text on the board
COMPVAL_TYPE_TOP: FIGURE | SIZE | 0.508 | 0.8 | 0.8999 | 0.9144 | 1.0 | 2.4 | DRILL CHART: TOP to BOTTOM | ALL UNITS ARE IN MILLIMETERS | PLATED | QTY | 121 | 14 | 200 | 2 | 4
